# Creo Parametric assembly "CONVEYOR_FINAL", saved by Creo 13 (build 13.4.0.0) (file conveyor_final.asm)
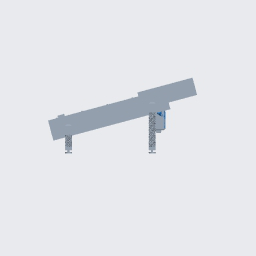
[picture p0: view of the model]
Units: millimeter Newton Second (mmNs); MM, TONNE, SECS

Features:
  1. datum plane "ASM_RIGHT"
  2. datum plane "ASM_TOP"
  3. datum plane "ASM_FRONT"
  4. coordinate system
  5. component "CONVEYOR"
